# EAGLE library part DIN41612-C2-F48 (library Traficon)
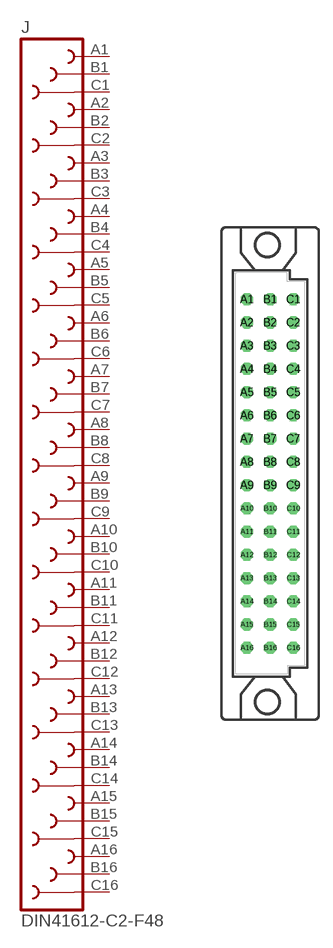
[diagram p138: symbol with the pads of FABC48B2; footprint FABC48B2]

Designator prefix J

## DIN41612-C2-F48  [FABC48B2]
A1  A1  pas
A2  A2  pas
A3  A3  pas
A4  A4  pas
A5  A5  pas
A6  A6  pas
A7  A7  pas
A8  A8  pas
A9  A9  pas
A10  A10  pas
A11  A11  pas
A12  A12  pas
A13  A13  pas
A14  A14  pas
A15  A15  pas
A16  A16  pas
B1  B1  pas
B2  B2  pas
B3  B3  pas
B4  B4  pas
B5  B5  pas
B6  B6  pas
B7  B7  pas
B8  B8  pas
B9  B9  pas
B10  B10  pas
B11  B11  pas
B12  B12  pas
B13  B13  pas
B14  B14  pas
B15  B15  pas
B16  B16  pas
C1  C1  pas
C2  C2  pas
C3  C3  pas
C4  C4  pas
C5  C5  pas
C6  C6  pas
C7  C7  pas
C8  C8  pas
C9  C9  pas
C10  C10  pas
C11  C11  pas
C12  C12  pas
C13  C13  pas
C14  C14  pas
C15  C15  pas
C16  C16  pas

## Footprint FABC48B2 (pad centres in mm)
CONNECTOR female, 48 pins, type C/2, rows ABC, grid 2.54 mm
drill 0.813 octagon: A1 -1.27,19.05; A2 -1.27,16.51; A3 -1.27,13.97; A4 -1.27,11.43; A5 -1.27,8.89; A6 -1.27,6.35; A7 -1.27,3.81; A8 -1.27,1.27; A9 -1.27,-1.27; A10 -1.27,-3.81; A11 -1.27,-6.35; A12 -1.27,-8.89; A13 -1.27,-11.43; A14 -1.27,-13.97; A15 -1.27,-16.51; A16 -1.27,-19.05; B1 1.27,19.05; B2 1.27,16.51; B3 1.27,13.97; B4 1.27,11.43; B5 1.27,8.89; B6 1.27,6.35; B7 1.27,3.81; B8 1.27,1.27; B9 1.27,-1.27; B10 1.27,-3.81; B11 1.27,-6.35; B12 1.27,-8.89; B13 1.27,-11.43; B14 1.27,-13.97; B15 1.27,-16.51; B16 1.27,-19.05; C1 3.81,19.05; C2 3.81,16.51; C3 3.81,13.97; C4 3.81,11.43; C5 3.81,8.89; C6 3.81,6.35; C7 3.81,3.81; C8 3.81,1.27; C9 3.81,-1.27; C10 3.81,-3.81; C11 3.81,-6.35; C12 3.81,-8.89; C13 3.81,-11.43; C14 3.81,-13.97; C15 3.81,-16.51; C16 3.81,-19.05
hole 2.794 at 0.965,-25
hole 2.794 at 0.965,25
